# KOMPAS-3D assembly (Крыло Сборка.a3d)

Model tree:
1. Массив по концентрической сетке:1  (labels: Экземпляр ( 1, 1 ); Экземпляр ( 1, 2 ))
     N 2 = 2; Шаг 2 = 360; Номер 2 = 1; Расстояние = -157

Referenced files in C:\Andrew\aviamodels\Крыло\: Трубка.m3d, Крыло.m3d, Элерон.m3d, Законцовка.m3d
